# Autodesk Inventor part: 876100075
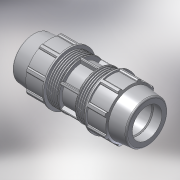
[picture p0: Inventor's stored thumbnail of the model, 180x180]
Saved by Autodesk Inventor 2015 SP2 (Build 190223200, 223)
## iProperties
Created: 2017-02
Part Number: 876100075
Material: PVC-Piping
Description: PLASSON REPAIR COUPLER 75
Document SubType Name: Modeling
Designer: KIM
Mass: 2387.75 g
Surface Area: 2478.17 cm^2
Volume: 1705.54 cm^3
Density: 1.4 g/cm^3
Appearance: Smooth - White
Author: KIM
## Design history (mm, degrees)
derived "87610.ipt"
feature "Solid1::87610.ipt"
tag "TaggingFeature1"
body "Solid1"
other parameters: "d1" = 289, "d2" = 75, "d4" = 24.08333, "d5" = 41.28571, "d7" = 132, "d8" = 99, "d9" = 41.28571, "d11" = 4.12857, "d12" = 105.6, "d13" = 120 deg, "d14" = 105, "d15" = 6 deg, "d16" = 118.8, "d18" = 3.75, "d19" = 35 deg, "d20" = 17.5 deg, "d21" = 122.76, "d23" = 0, "d25" = 360 deg, "d27" = 2.64, "d33" = 1.5, "d34" = 6.6, "d36" = 0, "d37" = 1.5, "d38" = 1.5, "d40" = 360 deg, "d42" = 52.02, "d46" = 2.25, "d50" = 3.6125, "d51" = 0, "d53" = 2.64229, "d54" = 2.64229, "d57" = 5.28457, "d62" = 116.424, "d_" = 75, "E_" = 132, "H_" = 289, "l_" = 143, "d52" = 26.42286
